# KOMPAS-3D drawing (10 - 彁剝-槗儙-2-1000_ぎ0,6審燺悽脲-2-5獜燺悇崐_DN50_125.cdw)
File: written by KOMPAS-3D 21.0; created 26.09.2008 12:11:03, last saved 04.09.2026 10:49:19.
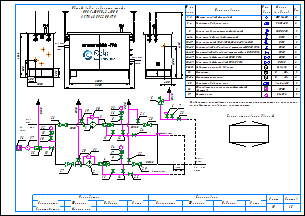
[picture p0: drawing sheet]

Sheets 1-2: A3, landscape

Document properties: Наименование: Макро:21; Автор: RaskoAdmin; Форматы листов документа: 2xA3; Полное имя файла: \\UR38nt01\Departments\КТО\КБ ПУРДГ\Заявки\Прайс-лист на типовые шкафы ГРПШ\ПРДГ_стандарт_20_03_2026\ПРДГ с РДНК\ПРДГ-ШУГО-2-1000_до0,6МПа_Рвых-2-5кПа_РДНК_DN50_125.cdw

Title block, sheet 1: Наименование: Пункт учета газа / ПУГ-Ш-400-Р / ЛГТИ.485922.001ТУ; designation: ЛГТИ.03.4411141; sheet number: 1; Количество листов документа: 2; organisation: ООО "ЭЛЬСТЕР Газэлектроника"; Форматы листов документа: A3; stored path: C:\Рабочие документы\Компас\ПУГ\Схема.cdw; Разработал: Устинов; Проверил: Кошкин; Утвердил: Кошкин
Title block, sheet 2: sheet number: 2; stored path: D:\Рабочие документы\Заявки\ПУРДГ\ПУРДГ-ШУЭО-2-100-Р 4411220.cdw; designation, second copy: ЛГТИ.03.4411141-

Views: Вид 1, Вид 2
Referenced files: wcvoit.frw
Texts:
  Normal
  Вход
  газа
  PDI
  Выход
  Р=     кПа
  DN125
  DN50
  DN20
  Импульс DN20
  ≥5DN
  HYSWLongFangSong
  № на
  схеме
  Усл.
  обозн.
  Марка
  (модель)
  Кол.
  Фильтр газовый фланцевый
  ФГ 16-50
  Регулятор давления газа
  РДНК-50
  Клапан предохранительный сбросной
  КПС DN20
  Кран шаровой газовый латунный
  DN15
  Кран кнопочный VE-РАСКО-НЗ-1,6-G1/2-М20
  Кран шаровой "под приварку" штуцерный DN20 PN16
  Кран шаровой "под приварку" штуцерный п/п DN20 PN16
  Кран шаровой фланцевый DN50 PN16
  Кран шаровой фланцевый DN125 PN16
  Индикатор перепада давления
  Delta 15
  Манометр
  Манометр-напоромер
  0...     МПа
  0...     кПа
  Обогреватель газогорелочный шкафной
  (Эльтон")
  Счетчик газа
  Venio-A-15
  ОГШН
  BK-G1,6
  Общий вид и габариты шкафа
  ПРДГ-ШУГО-2-1000
  Выход газа
  Вход газа
  Схема открывания дверей
  logo-rasko-ge.png
  Предприятие изготовитель может заменять комплектующие на аналогичные,
  не ухудшающие заявленных характеристик.
  Р=        МПа
  Должность
  Конструктор
  Фамилия
  Подпись
  Дата
  Согласовано
  Максимкин
  Лист
  Листов
  POLYLINE_STYLE_0.18_RGB_0_0_0
  POLYLINE_STYLE_0.50_RGB_0_0_0
  POLYLINE_STYLE_0.34_RGB_0_0_0
  PHANTOM_RGB_0_0_0_SC_1_THICK_0.18
  K5LT_THIN_RGB_0_0_0_THICK_0.18
  K5LT32769_RGB_0_0_0_THICK_0.18
  K5LT12_RGB_0_0_0_SC_1_THICK_0.18
  K5LT_DASHED_RGB_0_0_0_SC_1_THICK_0.18
  ACISOTGL_RGB_0_0_0_SC_0.8_THICK_0.25
  CONTINUOUS_RGB_0_127_31_THICK_0.3
  CONTINUOUS_RGB_0_0_255_THICK_0.35
  CONTINUOUS_RGB_255_0_0_THICK_0.35
  POLYLINE_STYLE_0.25_RGB_0_0_0
  CONTINUOUS_RGB_0_0_0_THICK_0.5
  POLYLINE_STYLE_0.35_RGB_0_0_255
  CONTINUOUS_RGB_0_0_0_THICK_0.4
  CONTINUOUS_RGB_0_0_0_THICK_0.35
  Без оформления
Dimensions and other numbers on the sheet: 1; 2; 3; 4; 5; 10; 27; 28; 29; 23; 8; 12; 18; 19; 20; 21; 22; 25; 24; 30; 31; 15; 16; 35; 36; 26; 6; 7; 11; 14; 13; 33; 1, 2; 3, 4; 6-14; 9; 15-17; 18-23; 24-25; 26-27; 28-29; 30-31; 32; 33-34; 37; 400; 1050; 500; 305; 2500; 1565; 2800; 17; 34; 1000; 4130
